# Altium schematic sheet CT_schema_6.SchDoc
size 391 x 301 mm
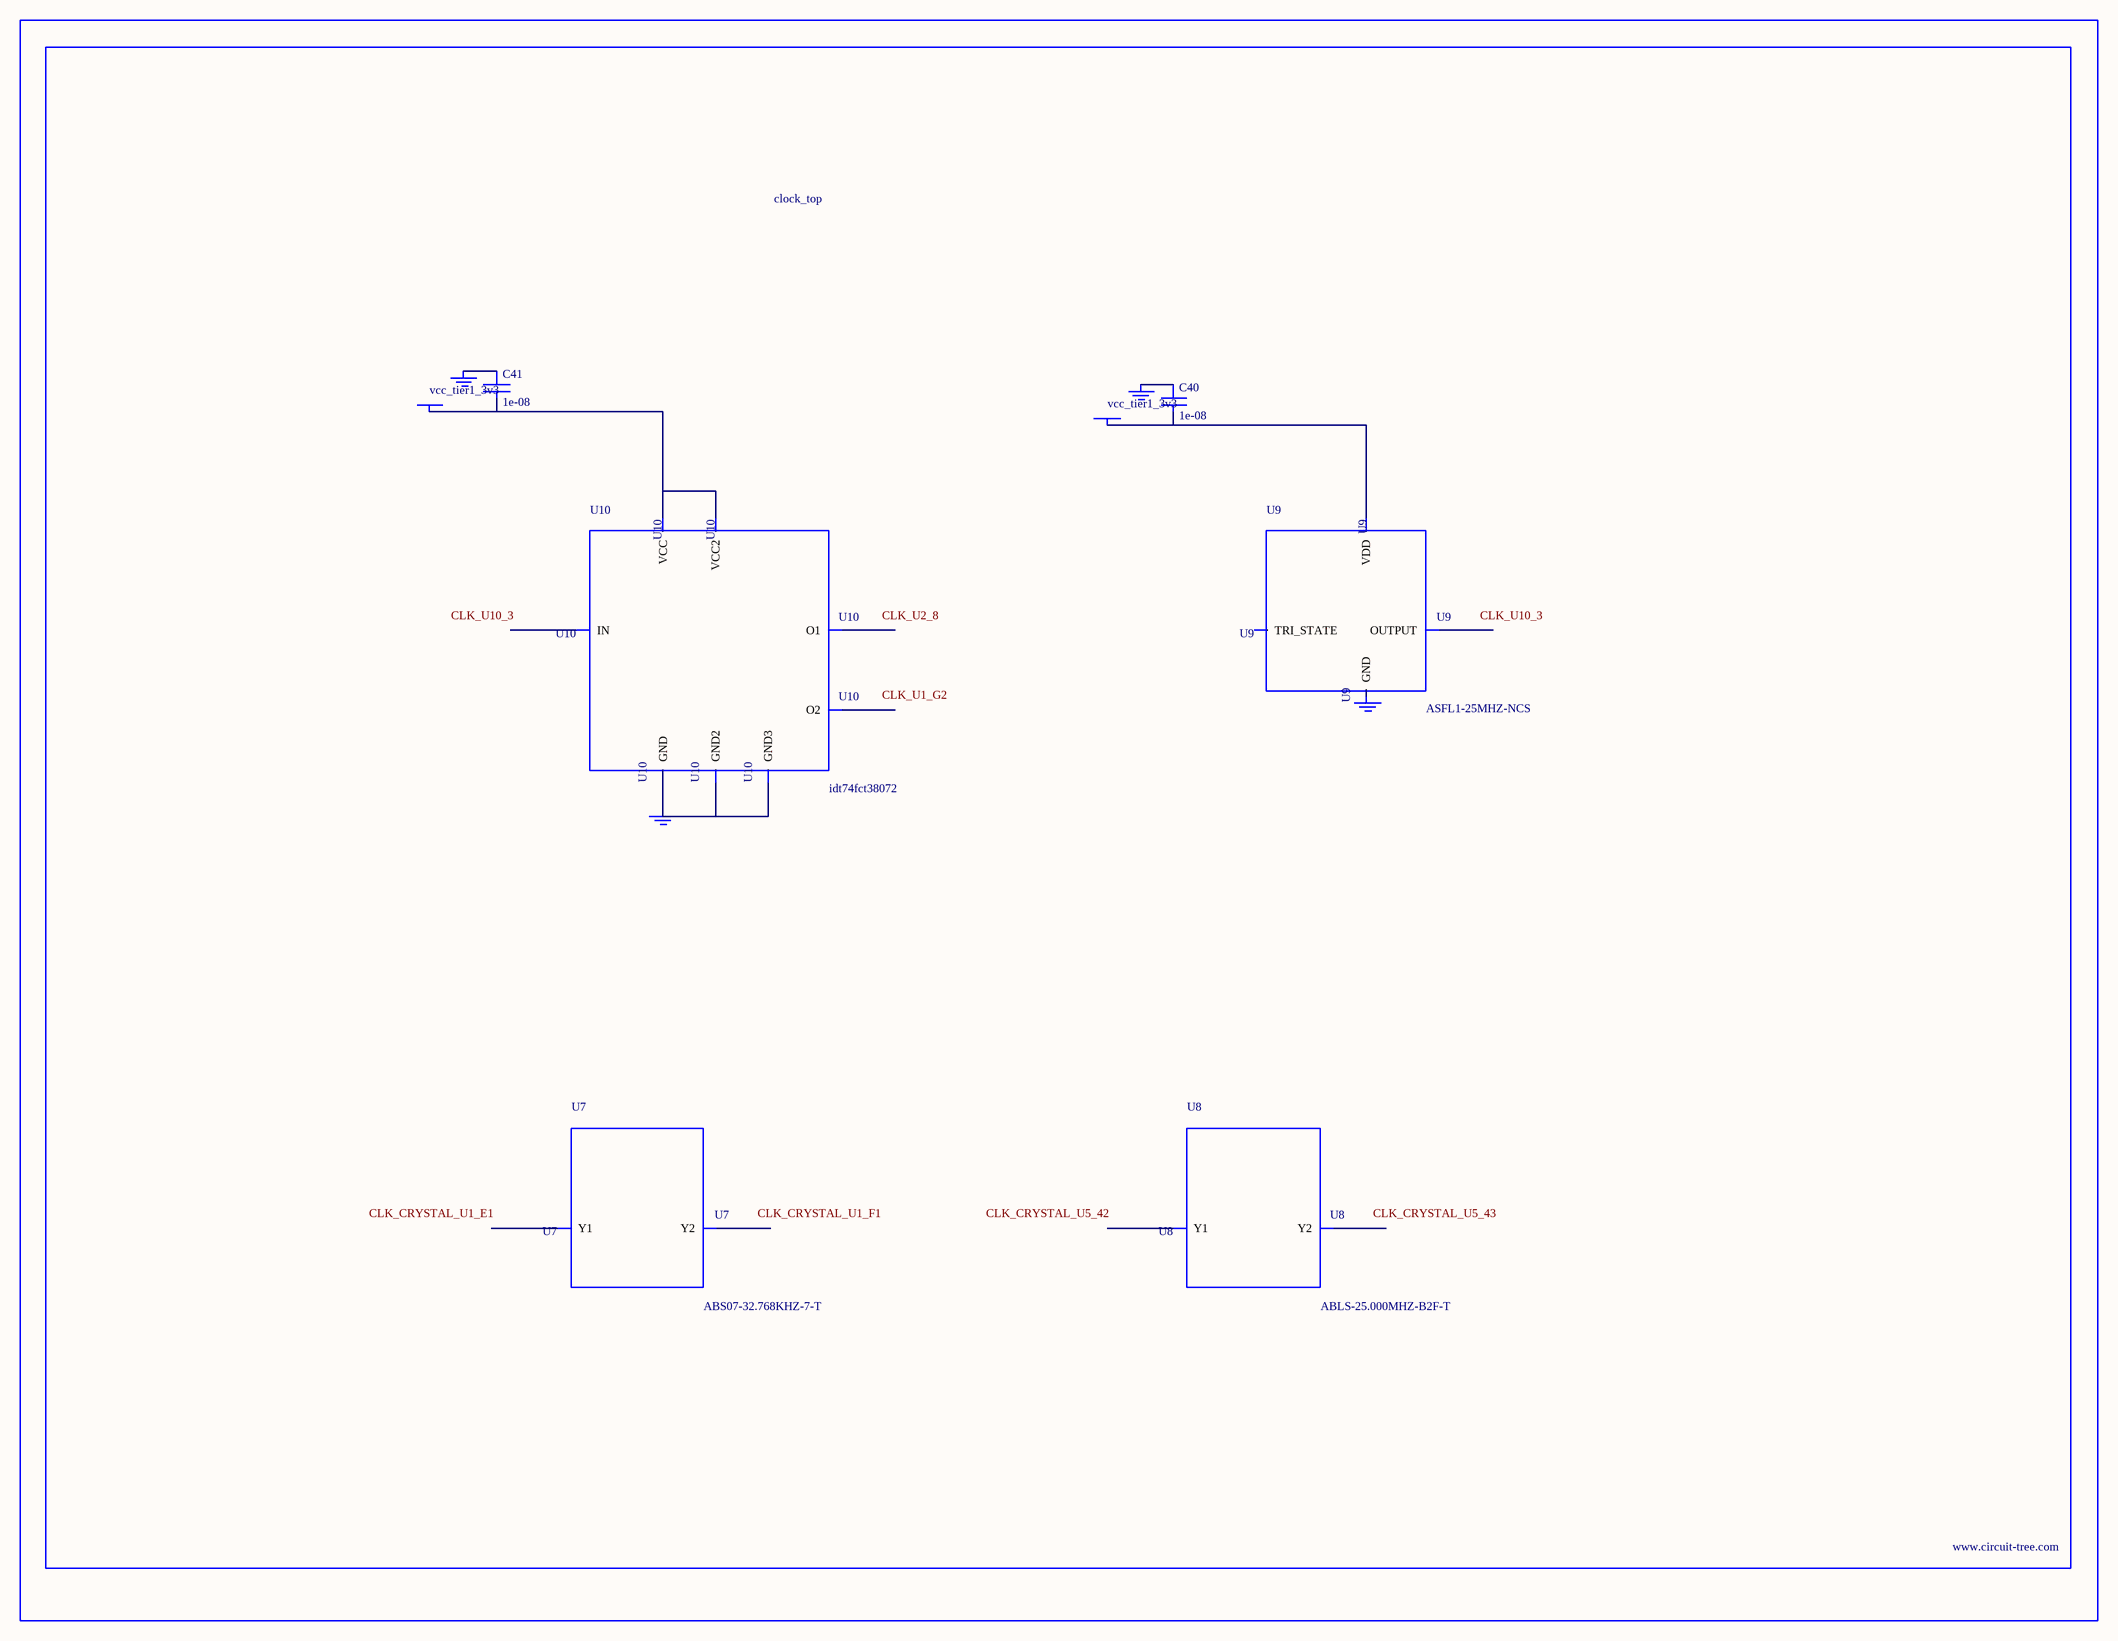
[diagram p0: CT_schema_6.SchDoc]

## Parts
BORDER5  (no value)
C40  1e-08  [C0402]
C41  1e-08  [C0402]
GND_INSTANCE_5_0  (no value)
GND_INSTANCE_5_1  (no value)
GND_INSTANCE_5_2  (no value)
GND_INSTANCE_5_3  (no value)
POWER_INSTANCE_5_0  vcc_tier1_3v3
POWER_INSTANCE_5_1  vcc_tier1_3v3
U7  ABS07-32.768KHZ-7-T  [ABS07-32.768KHZ-7-T]
U8  ABLS-25.000MHZ-B2F-T  [ABLS-25.000MHZ-B2F-T]
U9  ASFL1-25MHZ-NCS  [ASFL1]
U10  idt74fct38072  [IDT74FCT38072]

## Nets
NetC40_1: C40.1 GND_INSTANCE_5_0.0(GND)
NetC40_2: C40.2 POWER_INSTANCE_5_0.0(PWR) U9.4(VDD)
NetC41_1: C41.1 GND_INSTANCE_5_2.0(GND)
NetC41_2: C41.2 POWER_INSTANCE_5_1.0(PWR) U10.1(VCC) U10.2(VCC2)
NetGND_INSTANCE_5_3_0: GND_INSTANCE_5_3.0(GND) U10.4(GND) U10.5(GND2) U10.8(GND3)

Not connected (* = marked no-connect by the designer): GND_INSTANCE_5_1 0(GND); U7 1(Y1) 2(Y2); U8 1(Y1) 2(Y2); U9 1(TRI_STATE) 2(GND) 3(OUTPUT); U10 3(IN) 6(O2) 7(O1)

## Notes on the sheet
- Labels drawn without touching a wire or pin: CLK_CRYSTAL_U1_E1, CLK_CRYSTAL_U1_F1, CLK_CRYSTAL_U5_42, CLK_CRYSTAL_U5_43, CLK_U1_G2, CLK_U2_8, CLK_U10_3

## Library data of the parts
BORDER5 = BORDER_PAGE5
C40 C41 = C0402C103K3RAC
GND_INSTANCE_5_0-GND_INSTANCE_5_3 = GND
POWER_INSTANCE_5_0 POWER_INSTANCE_5_1 = PWR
